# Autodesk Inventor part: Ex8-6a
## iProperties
Author: J. DESIGNER
Created: 2001-10
Part Number: Ex8-6a
Document SubType Name: Modeling
Designer: J. DESIGNER
Control State: 0
Master: False
Checked Out: False
PropertySet Name: Design Tracking Control
Shininess: 20.0
Angle Display Precision: 2
Document Length Units: 11272
Document Angle Units: 11286
Document Time Units: 11279
Document Mass Units: 11290
Document Length Units Precision: 3
Document Angle Units Precision: 2
Compacted: False
PropertySet Name: _Private Model Information
Density: 0.0
Volumn: 0.0
Area: 0.0
PropertySet Name: Model Information
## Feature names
1. Extrusion2
